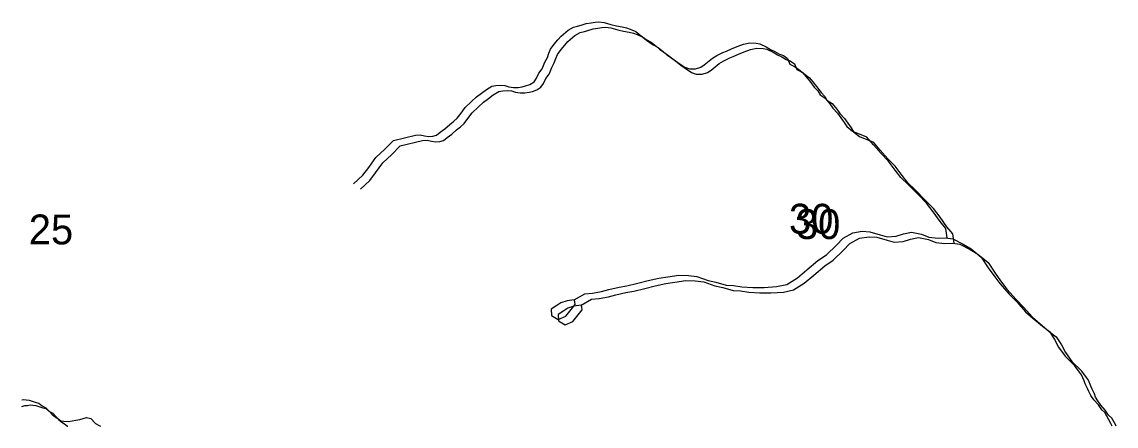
# Model space of a CAD drawing. Extents: x -21.1 to 50.3, y 0 to 22.1.
# Drawn here: x 43.456 to 44.99, y 14.846 to 15.412 of the extents above; entities that cross this region are included whole.
import ezdxf

# ---------------------------------------------------------------- set-up
doc = ezdxf.new("R2010")
doc.units = 0
for name, color, linetype in [('GM_X_Minor_Lake', 7, 'Continuous'), ('GM_X_Minor_River', 7, 'Continuous'), ('GM_X_Section_Text', 7, 'Continuous')]:
    doc.layers.add(name, color=color, linetype=linetype)

msp = doc.modelspace()

# ---------------------------------------------------------------- linework, layer by layer
at = {"layer": 'GM_X_Minor_Lake'}
for points in [[(44.2305, 15.0227), (44.2203, 15.0211), (44.2116, 15.0184), (44.206, 15.0149), (44.1981, 15.0096), (44.1985, 15.0005), (44.208, 14.9952), (44.2186, 14.9999), (44.2317, 15.0163), (44.2313, 15.0197)], [(44.2402, 15.0152), (44.23, 15.0136), (44.2213, 15.0109), (44.2156, 15.0074), (44.2077, 15.0021), (44.2082, 14.993), (44.2177, 14.9877), (44.2282, 14.9923), (44.2413, 15.0088), (44.2409, 15.0122)], [(44.2313, 15.0197), (44.2305, 15.0227)], [(44.2409, 15.0122), (44.2402, 15.0152)]]:
    msp.add_lwpolyline(points, dxfattribs=at)
at = {"layer": 'GM_X_Minor_River'}
for points in [[(43.9769, 15.2459), (44.0081, 15.2532), (44.0145, 15.254), (44.0206, 15.2526), (44.0267, 15.2515), (44.0324, 15.2519), (44.0374, 15.2535), (44.0427, 15.2577), (44.0491, 15.2623), (44.0559, 15.2681), (44.0615, 15.2727), (44.0664, 15.2773), (44.0717, 15.2842), (44.0777, 15.2922), (44.0864, 15.3006), (44.0936, 15.3068), (44.1004, 15.3122), (44.1072, 15.3172), (44.1151, 15.3218), (44.1204, 15.323), (44.1269, 15.3234), (44.133, 15.3231), (44.1387, 15.3212), (44.1452, 15.3201), (44.1516, 15.3202), (44.1573, 15.321), (44.1623, 15.3222), (44.1683, 15.3241), (44.174, 15.328), (44.1777, 15.3333), (44.1807, 15.3402), (44.1856, 15.3463), (44.1893, 15.3555), (44.1927, 15.3623), (44.1949, 15.3684), (44.1972, 15.3738), (44.2024, 15.3807), (44.2073, 15.3868), (44.2119, 15.3922), (44.2217, 15.4006), (44.2292, 15.4045), (44.2349, 15.406), (44.2399, 15.4076), (44.2471, 15.4096), (44.2539, 15.4107), (44.2596, 15.4116), (44.2645, 15.412), (44.2721, 15.4113), (44.2817, 15.4083), (44.2897, 15.4065), (44.2977, 15.405), (44.3038, 15.4036), (44.3087, 15.4017), (44.3167, 15.3983), (44.3221, 15.3938), (44.3313, 15.3874), (44.3382, 15.3837), (44.3454, 15.378), (44.3504, 15.3735), (44.3561, 15.3698), (44.363, 15.3645), (44.3703, 15.3588), (44.3776, 15.3536), (44.3852, 15.3487), (44.3917, 15.3461), (44.4001, 15.3462), (44.4077, 15.3485), (44.4126, 15.352), (44.4239, 15.3612), (44.4303, 15.365), (44.4387, 15.3693), (44.4436, 15.3712), (44.4508, 15.3743), (44.4587, 15.3774), (44.4678, 15.3809), (44.4766, 15.3825), (44.4853, 15.3822), (44.4906, 15.3811), (44.4994, 15.377), (44.5055, 15.3733), (44.5116, 15.3706), (44.5178, 15.3669), (44.5235, 15.365), (44.5292, 15.3605), (44.5327, 15.3529), (44.5392, 15.3496), (44.5446, 15.3458), (44.5503, 15.3409), (44.5549, 15.3356), (44.5603, 15.3288), (44.5668, 15.3205), (44.5718, 15.3152), (44.5749, 15.3099), (44.5822, 15.3051), (44.5887, 15.2971), (44.5929, 15.2911), (44.5994, 15.2843), (44.6041, 15.2775), (44.6087, 15.271), (44.6122, 15.2654), (44.6205, 15.2589)], [(43.9866, 15.2384), (44.0177, 15.2457), (44.0242, 15.2465), (44.0303, 15.2451), (44.0364, 15.244), (44.0421, 15.2444), (44.047, 15.246), (44.0523, 15.2502), (44.0587, 15.2548), (44.0655, 15.2606), (44.0712, 15.2652), (44.0761, 15.2698), (44.0813, 15.2767), (44.0874, 15.2847), (44.096, 15.2931), (44.1032, 15.2993), (44.11, 15.3047), (44.1168, 15.3097), (44.1247, 15.3143), (44.1301, 15.3155), (44.1365, 15.3159), (44.1426, 15.3156), (44.1483, 15.3137), (44.1548, 15.3126), (44.1613, 15.3127), (44.167, 15.3135), (44.1719, 15.3147), (44.178, 15.3166), (44.1836, 15.3205), (44.1874, 15.3258), (44.1904, 15.3327), (44.1953, 15.3388), (44.199, 15.348), (44.2023, 15.3548), (44.2046, 15.3609), (44.2068, 15.3663), (44.2121, 15.3732), (44.217, 15.3793), (44.2215, 15.3847), (44.2313, 15.3931), (44.2389, 15.397), (44.2446, 15.3985), (44.2495, 15.4001), (44.2567, 15.4021), (44.2635, 15.4032), (44.2692, 15.4041), (44.2742, 15.4045), (44.2818, 15.4038), (44.2913, 15.4008), (44.2993, 15.399), (44.3073, 15.3975), (44.3134, 15.3961), (44.3184, 15.3942), (44.3264, 15.3908), (44.3317, 15.3863), (44.3409, 15.3799), (44.3478, 15.3762), (44.3551, 15.3705), (44.36, 15.366), (44.3658, 15.3623), (44.3727, 15.357), (44.3799, 15.3513), (44.3872, 15.3461), (44.3949, 15.3412), (44.4013, 15.3386), (44.4097, 15.3387), (44.4173, 15.341), (44.4222, 15.3445), (44.4335, 15.3537), (44.44, 15.3575), (44.4483, 15.3618), (44.4532, 15.3637), (44.4604, 15.3668), (44.4684, 15.3699), (44.4775, 15.3734), (44.4862, 15.375), (44.495, 15.3747), (44.5003, 15.3736), (44.5091, 15.3695), (44.5152, 15.3658), (44.5213, 15.3631), (44.5274, 15.3594), (44.5331, 15.3575), (44.5389, 15.353), (44.5423, 15.3454), (44.5488, 15.3421), (44.5542, 15.3383), (44.5599, 15.3334), (44.5645, 15.3281), (44.5699, 15.3213), (44.5765, 15.313), (44.5814, 15.3077), (44.5845, 15.3024), (44.5918, 15.2976), (44.5983, 15.2896), (44.6026, 15.2836), (44.6091, 15.2768), (44.6137, 15.27), (44.6183, 15.2635), (44.6218, 15.2579), (44.6302, 15.2514)], [(44.6205, 15.2589), (44.6401, 15.2512)], [(43.921, 15.1852), (43.9342, 15.1974), (43.9424, 15.2081), (43.9525, 15.2222), (43.9649, 15.2337), (43.9769, 15.2459)], [(44.6302, 15.2514), (44.6497, 15.2437)], [(44.7529, 15.1093), (44.7511, 15.1225), (44.7431, 15.1323), (44.7335, 15.1459), (44.724, 15.158), (44.7126, 15.1697), (44.6985, 15.1844), (44.6882, 15.1938), (44.6802, 15.2044), (44.6702, 15.2172), (44.6603, 15.2278), (44.6496, 15.2398), (44.6401, 15.2512)], [(44.7626, 15.1018), (44.7608, 15.115), (44.7527, 15.1248), (44.7432, 15.1384), (44.7336, 15.1505), (44.7222, 15.1622), (44.7081, 15.1769), (44.6978, 15.1863), (44.6898, 15.1969), (44.6799, 15.2097), (44.67, 15.2203), (44.6593, 15.2323), (44.6497, 15.2437)], [(43.9307, 15.1777), (43.9438, 15.1899), (43.9521, 15.2006), (43.9622, 15.2147), (43.9746, 15.2262), (43.9866, 15.2384)], [(44.2305, 15.0227), (44.2452, 15.0312), (44.2558, 15.032), (44.2686, 15.0344), (44.2788, 15.0371), (44.2932, 15.0406), (44.3042, 15.0422), (44.3196, 15.0461), (44.334, 15.0497), (44.3491, 15.0528), (44.3616, 15.0548), (44.3771, 15.0572), (44.3903, 15.0569), (44.4024, 15.0555), (44.418, 15.0499), (44.429, 15.0473), (44.4434, 15.0432), (44.4536, 15.0426), (44.4653, 15.0407), (44.4808, 15.0401), (44.4964, 15.0398), (44.5137, 15.0411), (44.5281, 15.0442), (44.5432, 15.0535), (44.5563, 15.0646), (44.5717, 15.0776), (44.5838, 15.0856), (44.5977, 15.0994), (44.6071, 15.109), (44.6206, 15.1167), (44.6339, 15.1186), (44.6448, 15.118), (44.6593, 15.1139), (44.6691, 15.1109), (44.6816, 15.1118), (44.6918, 15.1153), (44.7031, 15.1176), (44.7171, 15.1147), (44.7274, 15.1106), (44.7402, 15.1092), (44.7508, 15.1096), (44.7611, 15.1082), (44.7755, 15.1007), (44.7865, 15.094), (44.8006, 15.0823), (44.8105, 15.0676), (44.8182, 15.0566), (44.827, 15.0453), (44.8399, 15.0306), (44.851, 15.0193), (44.8628, 15.0057), (44.8731, 14.997), (44.8864, 14.9857), (44.8963, 14.9782), (44.9036, 14.9673), (44.9089, 14.9563), (44.9181, 14.9438), (44.9318, 14.9303)], [(44.2402, 15.0152), (44.2548, 15.0237), (44.2654, 15.0245), (44.2783, 15.0269), (44.2885, 15.0296), (44.3028, 15.0331), (44.3138, 15.0347), (44.3293, 15.0386), (44.3436, 15.0422), (44.3587, 15.0453), (44.3712, 15.0473), (44.3867, 15.0497), (44.3999, 15.0494), (44.4121, 15.048), (44.4276, 15.0424), (44.4386, 15.0398), (44.453, 15.0357), (44.4632, 15.0351), (44.475, 15.0332), (44.4905, 15.0326), (44.506, 15.0323), (44.5234, 15.0336), (44.5377, 15.0367), (44.5528, 15.046), (44.566, 15.0571), (44.5814, 15.0701), (44.5934, 15.0781), (44.6073, 15.0919), (44.6167, 15.1015), (44.6303, 15.1092), (44.6435, 15.1111), (44.6545, 15.1105), (44.6689, 15.1064), (44.6787, 15.1034), (44.6912, 15.1043), (44.7014, 15.1078), (44.7127, 15.1101), (44.7268, 15.1072), (44.737, 15.1031), (44.7499, 15.1017), (44.7605, 15.1021), (44.7707, 15.1007), (44.7851, 15.0932), (44.7961, 15.0864), (44.8102, 15.0748), (44.8202, 15.0601), (44.8278, 15.0491), (44.8366, 15.0378), (44.8496, 15.0231), (44.8606, 15.0118), (44.8724, 14.9982), (44.8827, 14.9895), (44.896, 14.9782), (44.9059, 14.9707), (44.9132, 14.9598), (44.9186, 14.9488), (44.9277, 14.9363), (44.9415, 14.9228)], [(44.9695, 14.8687), (44.9649, 14.8755), (44.9587, 14.8826), (44.9545, 14.8887), (44.9514, 14.894), (44.9498, 14.8985), (44.9464, 14.9049), (44.9448, 14.9091), (44.9413, 14.9174), (44.9386, 14.9215), (44.9318, 14.9303)], [(44.9791, 14.8612), (44.9745, 14.868), (44.9684, 14.8751), (44.9641, 14.8812), (44.961, 14.8865), (44.9595, 14.891), (44.956, 14.8974), (44.9544, 14.9016), (44.951, 14.9099), (44.9483, 14.914), (44.9415, 14.9228)], [(43.4563, 14.8826), (43.4584, 14.883), (43.4622, 14.8827), (43.4664, 14.8823), (43.4721, 14.8801), (43.4763, 14.879), (43.48, 14.8778), (43.4846, 14.8741), (43.4899, 14.8714), (43.4945, 14.8669), (43.4987, 14.862), (43.5029, 14.8586), (43.5067, 14.8563), (43.5109, 14.8533), (43.515, 14.8525), (43.5215, 14.8522), (43.5321, 14.8542), (43.5374, 14.8549), (43.5423, 14.8565), (43.5468, 14.8577), (43.5529, 14.8562), (43.5593, 14.8494), (43.5647, 14.8467), (43.5664, 14.8458)], [(43.4563, 14.8732), (43.4564, 14.8732), (43.4605, 14.8744), (43.4643, 14.8748), (43.4681, 14.8755), (43.4719, 14.8752), (43.476, 14.8748), (43.4817, 14.8726), (43.4859, 14.8714), (43.4897, 14.8703), (43.4943, 14.8666), (43.4996, 14.8639), (43.5041, 14.8594), (43.5083, 14.8545), (43.5125, 14.8511), (43.5163, 14.8488), (43.5205, 14.8458), (43.5207, 14.8458)], [(44.9844, 14.8458), (44.9822, 14.8495), (44.9795, 14.8544), (44.9741, 14.8646), (44.9695, 14.8687)], [(44.9897, 14.8458), (44.9891, 14.8469), (44.9837, 14.8571), (44.9791, 14.8612)]]:
    msp.add_lwpolyline(points, dxfattribs=at)

# ---------------------------------------------------------------- texts
at = {"layer": 'GM_X_Section_Text'}
for s, p in [('30', (44.5313, 15.1153)), ('30', (44.541, 15.1078)), ('25', (43.466, 15.1003))]:
    msp.add_text(s, height=0.04186, rotation=0, dxfattribs=at).set_placement(p)

doc.saveas('drawing.dxf')
